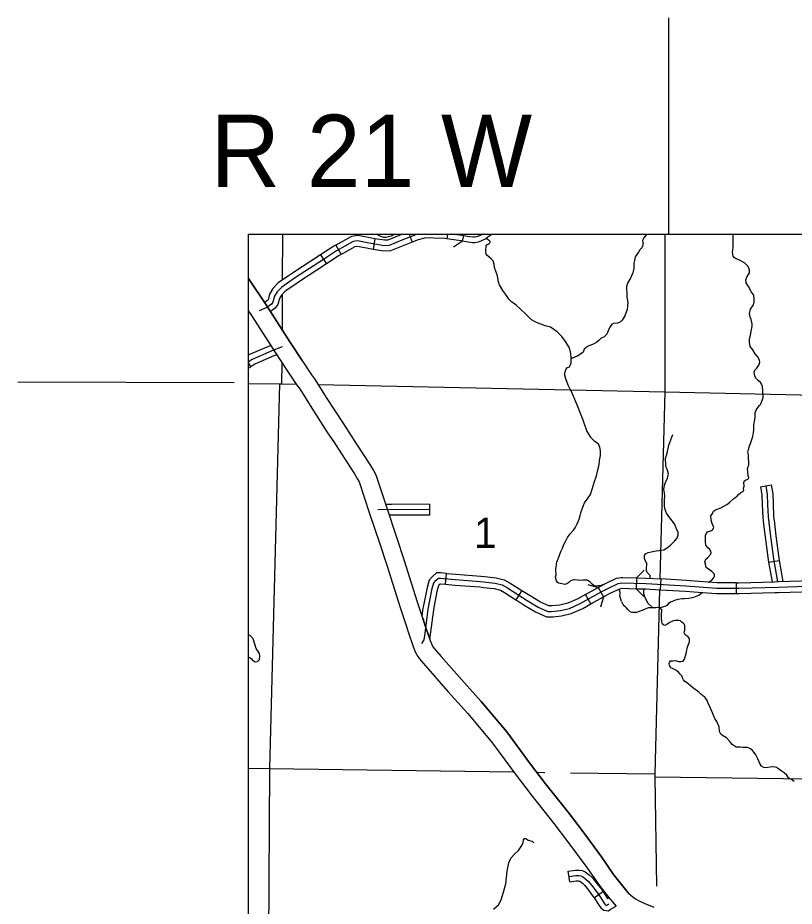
# Model space of a CAD drawing. Extents: x 813775 to 1157140, y 1757555 to 1979907.
# Drawn here: x 906132 to 927663, y 1862069 to 1886709 of the extents above; entities that cross this region are included whole.
import ezdxf

# ---------------------------------------------------------------- set-up
doc = ezdxf.new("R2010")
doc.units = 0
for name, color, linetype in [('Level 10', 7, 'Continuous'), ('Level 31', 7, 'Continuous'), ('Level 32', 7, 'Continuous'), ('Level 35', 7, 'Continuous'), ('Level 38', 7, 'Continuous'), ('Level 4', 7, 'Continuous'), ('Level 45', 7, 'Continuous'), ('Level 5', 7, 'Continuous'), ('R_Dimension', 7, 'Continuous'), ('R_Draft', 7, 'Continuous')]:
    doc.layers.add(name, color=color, linetype=linetype)

msp = doc.modelspace()

# ---------------------------------------------------------------- linework, layer by layer
at = {"layer": 'Level 10'}
for p, q in [((914014, 1877207), (914013, 1877209)), ((916840, 1871686), (916841, 1871683)), ((916840, 1871686), (916841, 1871683)), ((918436, 1868354), (918434, 1868357)), ((923059, 1862439), (923199, 1862322)), ((923199, 1862322), (923190, 1862329))]:
    msp.add_line(p, q, dxfattribs=at)
for points in [[(912532, 1879482), (913034, 1878721), (913678, 1877720), (914014, 1877207)], [(914014, 1877207), (913678, 1877720), (913034, 1878721), (912532, 1879482)], [(912532, 1878574), (912615, 1878448), (913259, 1877447), (913596, 1876933)], [(912532, 1878574), (912615, 1878448), (913259, 1877447), (913596, 1876933)], [(912532, 1878574), (912615, 1878448), (913259, 1877447), (913596, 1876933)], [(914013, 1877209), (914281, 1876809), (914364, 1876696), (914704, 1876152), (915143, 1875474), (915313, 1875217), (915527, 1874885), (915898, 1874321), (915995, 1874153), (916057, 1874032), (916354, 1873144), (916646, 1872279), (916840, 1871686)], [(914013, 1877209), (914281, 1876809), (914364, 1876696), (914704, 1876152), (915143, 1875474), (915313, 1875217), (915527, 1874885), (915898, 1874321), (915995, 1874153), (916057, 1874032), (916354, 1873144), (916646, 1872279), (916840, 1871686)], [(913596, 1876933), (913872, 1876521), (913950, 1876415), (914282, 1875883), (914724, 1875200), (914894, 1874944), (915108, 1874612), (915472, 1874058), (915556, 1873914), (915595, 1873838), (915880, 1872985), (916172, 1872122), (916364, 1871531)], [(913596, 1876933), (913872, 1876521), (913950, 1876415), (914282, 1875883), (914724, 1875200), (914894, 1874944), (915108, 1874612), (915472, 1874058), (915556, 1873914), (915595, 1873838), (915880, 1872985), (916172, 1872122), (916364, 1871531)], [(913596, 1876933), (913872, 1876521), (913950, 1876415), (914282, 1875883), (914724, 1875200), (914894, 1874944), (915108, 1874612), (915472, 1874058), (915556, 1873914), (915595, 1873838), (915880, 1872985), (916172, 1872122), (916364, 1871531)], [(916841, 1871683), (917207, 1870512), (917359, 1870068), (917359, 1870067), (917361, 1870062), (917364, 1870051), (917370, 1870038), (917431, 1869832), (917570, 1869441), (917611, 1869325), (917646, 1869261), (917650, 1869256), (917692, 1869204), (917877, 1868992), (918436, 1868354)], [(916841, 1871683), (917207, 1870512), (917359, 1870068), (917359, 1870067), (917361, 1870062), (917364, 1870051), (917370, 1870038), (917431, 1869832), (917570, 1869441), (917611, 1869325), (917646, 1869261), (917650, 1869256), (917692, 1869204), (917877, 1868992), (918436, 1868354)], [(916364, 1871531), (916732, 1870356), (916894, 1869885), (916956, 1869677), (917099, 1869273), (917154, 1869120), (917221, 1868997), (917250, 1868955), (917309, 1868882), (917501, 1868663), (918060, 1868025)], [(916364, 1871531), (916732, 1870356), (916894, 1869885), (916956, 1869677), (917099, 1869273), (917154, 1869120), (917221, 1868997), (917250, 1868955), (917309, 1868882), (917501, 1868663), (918060, 1868025)], [(916364, 1871531), (916732, 1870356), (916894, 1869885), (916956, 1869677), (917099, 1869273), (917154, 1869120), (917221, 1868997), (917250, 1868955), (917309, 1868882), (917501, 1868663), (918060, 1868025)], [(918434, 1868357), (918986, 1867743), (919693, 1866904), (920352, 1866007), (920764, 1865465), (921391, 1864674), (921780, 1864165), (922317, 1863435), (922652, 1862952), (922801, 1862763), (922945, 1862584), (923061, 1862437)], [(923061, 1862437), (922945, 1862584), (922801, 1862763), (922652, 1862952), (922317, 1863435), (921780, 1864165), (921391, 1864674), (920764, 1865465), (920352, 1866007), (919693, 1866904), (918986, 1867743), (918434, 1868357)], [(918060, 1868025), (918608, 1867414), (919300, 1866594), (919952, 1865708), (920369, 1865158), (920996, 1864367), (921380, 1863865), (921911, 1863144), (922250, 1862655), (922410, 1862452), (922557, 1862269), (922721, 1862069)], [(918060, 1868025), (918608, 1867414), (919300, 1866594), (919952, 1865708), (920369, 1865158), (920996, 1864367), (921380, 1863865), (921911, 1863144), (922250, 1862655), (922410, 1862452), (922557, 1862269), (922706, 1862088)], [(918060, 1868025), (918608, 1867414), (919300, 1866594), (919952, 1865708), (920369, 1865158), (920996, 1864367), (921380, 1863865), (921911, 1863144), (922250, 1862655), (922410, 1862452), (922557, 1862269), (922721, 1862069)], [(923190, 1862329), (923261, 1862276), (923325, 1862235), (923378, 1862207), (923520, 1862147), (923769, 1862044)]]:
    msp.add_lwpolyline(points, dxfattribs=at)
at = {"layer": 'Level 31'}
for p, q in [((914527, 1880134), (914690, 1879883)), ((917992, 1871002), (918021, 1871300))]:
    msp.add_line(p, q, dxfattribs=at)
for points in [[(914527, 1880134), (913749, 1879629), (913640, 1879553)], [(914608, 1880009), (913833, 1879504), (913453, 1879241), (913329, 1879112), (913253, 1878987), (913208, 1878826), (913164, 1878763), (913034, 1878674), (912825, 1878585)], [(914690, 1879883), (913916, 1879380), (913811, 1879307)], [(913640, 1879553), (913356, 1879356), (913209, 1879204), (913114, 1879047), (913071, 1878891), (913057, 1878872), (912973, 1878814)], [(913811, 1879307), (913551, 1879126), (913448, 1879019), (913392, 1878926), (913346, 1878760), (913270, 1878655), (913136, 1878562)], [(913811, 1879307), (913551, 1879126), (913448, 1879019), (913392, 1878926), (913346, 1878760), (913270, 1878655), (913143, 1878567)], [(918021, 1871300), (917866, 1871316), (917745, 1871316), (917628, 1871214), (917536, 1871110), (917481, 1870911), (917384, 1870414)], [(918021, 1871300), (918275, 1871275), (918973, 1871222), (919075, 1871211)], [(919075, 1871211), (919394, 1871176), (919622, 1871120), (919786, 1871033), (920109, 1870822)], [(922227, 1870911), (922257, 1870928), (922444, 1871029), (922736, 1871163), (922868, 1871187), (922902, 1871186)], [(922902, 1871186), (923288, 1871176), (923283, 1870876)], [(923288, 1871176), (923565, 1871169), (923962, 1871146)], [(917678, 1870356), (917773, 1870842), (917807, 1870964), (917840, 1871001), (917856, 1871015), (917992, 1871002)], [(917992, 1871002), (918249, 1870976), (918946, 1870923), (919042, 1870912)], [(919042, 1870912), (919342, 1870880), (919514, 1870838), (919633, 1870774), (919944, 1870571)], [(921877, 1870717), (922227, 1870911)], [(922227, 1870911), (922373, 1870649), (922402, 1870665), (922578, 1870760), (922827, 1870875), (922891, 1870886), (922894, 1870886)], [(926061, 1871040), (926127, 1871040), (927113, 1871068)], [(927113, 1871068), (927222, 1871071), (928168, 1871101)], [(922894, 1870886), (923283, 1870876)], [(923283, 1870876), (923552, 1870869), (923945, 1870847)], [(926061, 1870740), (926132, 1870740), (927121, 1870768)], [(927121, 1870768), (927231, 1870771), (928177, 1870802)], [(917384, 1870414), (917368, 1870336), (917340, 1870123), (917424, 1869857), (917431, 1869832), (917437, 1869816), (917462, 1869747), (917518, 1869588), (917554, 1869486)], [(922023, 1870455), (922373, 1870649)], [(917554, 1869486), (917576, 1869609), (917665, 1870288), (917678, 1870356)]]:
    msp.add_lwpolyline(points, dxfattribs=at)
at = {"layer": 'Level 32'}
for p, q in [((916035, 1880582), (915983, 1880287)), ((916984, 1880709), (917070, 1880490)), ((918046, 1880709), (918028, 1880577)), ((914949, 1880403), (915095, 1880141)), ((912532, 1877117), (912593, 1877028)), ((921444, 1862746), (921397, 1863042)), ((922116, 1862300), (922359, 1862477))]:
    msp.add_line(p, q, dxfattribs=at)
for points in [[(917232, 1880709), (917190, 1880698), (916780, 1880538), (916432, 1880395), (916290, 1880386), (915826, 1880466), (915549, 1880520), (915433, 1880502), (914970, 1880243), (914608, 1880009)], [(916035, 1880582), (915853, 1880614), (915552, 1880672), (915384, 1880646), (914949, 1880403)], [(916807, 1880709), (916724, 1880677), (916398, 1880543), (916298, 1880537), (916035, 1880582)], [(918028, 1880577), (917972, 1880584), (917673, 1880593), (917445, 1880609), (917237, 1880555), (917070, 1880490)], [(918459, 1880515), (918424, 1880522), (918285, 1880541), (918028, 1880577)], [(918450, 1880670), (918305, 1880689), (918164, 1880709)], [(919033, 1880709), (919029, 1880706), (918931, 1880660), (918855, 1880634), (918793, 1880621), (918751, 1880621), (918593, 1880640), (918450, 1880670)], [(918499, 1880709), (918459, 1880515)], [(919162, 1880620), (919108, 1880577), (918987, 1880521), (918896, 1880489), (918809, 1880471), (918741, 1880471), (918569, 1880492), (918459, 1880515)], [(919255, 1880709), (919233, 1880675), (919162, 1880620)], [(914949, 1880403), (914892, 1880372), (914527, 1880135)], [(915983, 1880287), (915799, 1880319), (915546, 1880368), (915483, 1880358), (915095, 1880141)], [(917070, 1880490), (916836, 1880398), (916466, 1880247), (916281, 1880235), (915983, 1880287)], [(915095, 1880141), (915047, 1880115), (914690, 1879883)], [(913146, 1877623), (912557, 1877367), (912532, 1877350)], [(913313, 1877364), (913230, 1877333), (912703, 1877104), (912593, 1877028)], [(912593, 1877028), (912542, 1876992), (912532, 1876981)], [(921397, 1863042), (921595, 1863074), (921703, 1863074), (921783, 1863057), (921865, 1863027), (921980, 1862938), (922072, 1862854), (922194, 1862695), (922314, 1862539), (922359, 1862477)], [(921420, 1862894), (921607, 1862924), (921687, 1862924), (921742, 1862912), (921792, 1862894), (921883, 1862823), (921961, 1862753), (922075, 1862604), (922194, 1862449), (922280, 1862330), (922372, 1862184), (922415, 1862122), (922442, 1862102), (922470, 1862099), (922495, 1862115), (922526, 1862133)], [(921444, 1862746), (921619, 1862774), (921672, 1862774), (921701, 1862768), (921719, 1862761), (921787, 1862709), (921850, 1862651), (921956, 1862513), (922073, 1862359), (922116, 1862300)], [(922116, 1862300), (922156, 1862246), (922247, 1862101), (922306, 1862017), (922387, 1861956), (922508, 1861946), (922571, 1861986), (922721, 1862069)], [(922359, 1862477), (922405, 1862414), (922487, 1862283), (922526, 1862309)]]:
    msp.add_lwpolyline(points, dxfattribs=at)
at = {"layer": 'Level 35'}
for points in [[(916280, 1880618), (916202, 1880640), (916125, 1880684), (916083, 1880709)], [(916589, 1880709), (916568, 1880703), (916487, 1880655), (916371, 1880620), (916336, 1880615), (916280, 1880618)], [(919215, 1880523), (919188, 1880544), (919160, 1880568), (919135, 1880598)], [(919214, 1880462), (919223, 1880474), (919232, 1880485), (919232, 1880494), (919230, 1880503), (919225, 1880513), (919215, 1880523)], [(923571, 1880709), (923570, 1880699), (923530, 1880651), (923488, 1880606), (923459, 1880531), (923469, 1880478), (923470, 1880477)], [(925974, 1880343), (925971, 1880520), (925966, 1880658), (925978, 1880709)], [(919397, 1879655), (919355, 1879781), (919342, 1879866), (919310, 1879967), (919257, 1880023), (919193, 1880076), (919140, 1880121), (919116, 1880153), (919111, 1880214), (919111, 1880286), (919119, 1880358), (919124, 1880387), (919143, 1880408), (919172, 1880427), (919201, 1880446), (919214, 1880462)], [(923470, 1880477), (923456, 1880378), (923435, 1880327), (923384, 1880269), (923342, 1880213), (923296, 1880146), (923254, 1880075), (923230, 1879974), (923211, 1879899), (923219, 1879769)], [(926329, 1879356), (926324, 1879445), (926351, 1879516), (926396, 1879591), (926420, 1879636), (926422, 1879721), (926385, 1879809), (926295, 1879902), (926167, 1879979), (926077, 1880019), (926003, 1880053), (925966, 1880101), (925952, 1880197), (925974, 1880343)], [(923219, 1879769), (923188, 1879634), (923116, 1879470), (923047, 1879369), (923012, 1879257), (923007, 1879193), (923023, 1879058), (923023, 1878957), (923049, 1878813), (923039, 1878707), (923034, 1878614), (922964, 1878444)], [(920902, 1878129), (920757, 1878167), (920516, 1878254), (920380, 1878331), (920213, 1878494), (920075, 1878627), (919955, 1878741), (919878, 1878791), (919830, 1878826), (919785, 1878868), (919753, 1878906), (919700, 1878980), (919586, 1879148), (919488, 1879307), (919461, 1879379), (919448, 1879501), (919427, 1879581), (919397, 1879655)], [(926425, 1878506), (926452, 1878627), (926531, 1878744), (926550, 1878835), (926555, 1878909), (926539, 1879015), (926481, 1879100), (926391, 1879255), (926329, 1879356)], [(922964, 1878444), (922894, 1878320), (922838, 1878264), (922761, 1878238), (922647, 1878227), (922609, 1878209), (922554, 1878124), (922500, 1878025), (922469, 1877932), (922392, 1877860), (922312, 1877823), (922254, 1877765), (922179, 1877706), (922089, 1877653)], [(926704, 1877216), (926643, 1877318), (926582, 1877387), (926513, 1877496), (926438, 1877595), (926420, 1877714), (926420, 1877807), (926446, 1877895), (926465, 1878020), (926497, 1878145), (926497, 1878225), (926473, 1878339), (926444, 1878408), (926425, 1878506)], [(921473, 1877265), (921467, 1877395), (921430, 1877552), (921316, 1877735), (921220, 1877874), (921085, 1877999), (920902, 1878129)], [(922089, 1877653), (921927, 1877592), (921842, 1877517), (921810, 1877435), (921736, 1877382), (921645, 1877321), (921513, 1877270), (921473, 1877265)], [(921472, 1876370), (921398, 1876524), (921326, 1876695), (921297, 1876833), (921318, 1876912), (921329, 1876958), (921377, 1877006), (921430, 1877032), (921448, 1877069), (921475, 1877144), (921473, 1877265)], [(926749, 1876034), (926786, 1876123), (926802, 1876182), (926800, 1876227), (926792, 1876362), (926784, 1876487), (926736, 1876588), (926667, 1876652), (926608, 1876708), (926571, 1876766), (926558, 1876838), (926553, 1876878), (926574, 1876934), (926624, 1876995), (926661, 1877043), (926688, 1877091), (926707, 1877154), (926704, 1877216)], [(921472, 1876370), (921624, 1876002), (921804, 1875555), (921910, 1875234), (922014, 1875082), (922131, 1874957)], [(926539, 1875275), (926545, 1875409), (926561, 1875524), (926584, 1875619), (926582, 1875675), (926584, 1875763), (926603, 1875824), (926638, 1875877), (926701, 1875952), (926736, 1875991), (926749, 1876034)], [(924103, 1874307), (924095, 1874486), (924135, 1874638), (924185, 1874856), (924297, 1875156)], [(926449, 1874898), (926489, 1875015), (926515, 1875097), (926534, 1875211), (926539, 1875275)], [(922261, 1874428), (922295, 1874571), (922292, 1874699), (922276, 1874802), (922234, 1874888), (922131, 1874957)], [(926401, 1874300), (926407, 1874395), (926399, 1874480), (926391, 1874584), (926375, 1874661), (926393, 1874738), (926425, 1874837), (926449, 1874898)], [(922111, 1873825), (922178, 1874004), (922214, 1874170), (922243, 1874272), (922257, 1874335), (922262, 1874391), (922261, 1874428)], [(924065, 1873333), (924074, 1873453), (924063, 1873528), (924044, 1873639), (924063, 1873740), (924103, 1873844), (924151, 1873935), (924158, 1873990), (924172, 1874057), (924161, 1874126), (924135, 1874187), (924108, 1874246), (924103, 1874307)], [(926385, 1874006), (926375, 1874125), (926367, 1874204), (926385, 1874266), (926401, 1874300)], [(925878, 1873276), (925982, 1873365), (926029, 1873402), (926080, 1873440), (926120, 1873485), (926175, 1873530), (926252, 1873581), (926263, 1873618), (926258, 1873666), (926271, 1873716), (926274, 1873756), (926268, 1873793), (926266, 1873825), (926282, 1873868), (926322, 1873892), (926361, 1873902), (926393, 1873923), (926404, 1873961), (926385, 1874006), (926385, 1874027)], [(921748, 1872977), (921780, 1873093), (921817, 1873183), (921846, 1873259), (921945, 1873395), (922012, 1873492), (922063, 1873634), (922111, 1873825)], [(924355, 1872202), (924405, 1872264), (924445, 1872360), (924442, 1872432), (924397, 1872538), (924341, 1872676), (924217, 1872844), (924124, 1872969), (924084, 1873070), (924065, 1873168), (924065, 1873333)], [(925400, 1872507), (925432, 1872569), (925416, 1872622), (925390, 1872688), (925358, 1872773), (925350, 1872893), (925392, 1872962), (925427, 1873026), (925480, 1873063), (925631, 1873121), (925706, 1873161), (925791, 1873212), (925878, 1873276)], [(921374, 1872291), (921440, 1872390), (921541, 1872497), (921584, 1872568), (921644, 1872674), (921703, 1872802), (921730, 1872903), (921748, 1872977)], [(925263, 1871743), (925339, 1871821), (925358, 1871869), (925352, 1871914), (925318, 1871959), (925268, 1872012), (925212, 1872084), (925201, 1872180), (925201, 1872243), (925201, 1872302), (925204, 1872352), (925220, 1872400), (925262, 1872451), (925368, 1872488), (925400, 1872507)], [(921083, 1871607), (921146, 1871779), (921192, 1871908), (921233, 1871998), (921270, 1872101), (921321, 1872183), (921374, 1872291)], [(923548, 1871618), (923511, 1871710), (923511, 1871755), (923513, 1871798), (923543, 1871840), (923617, 1871883), (923744, 1871904), (923835, 1871925), (924047, 1871957), (924143, 1872010), (924236, 1872085), (924355, 1872202)], [(921654, 1871108), (921568, 1871125), (921544, 1871118), (921463, 1871090), (921410, 1871046), (921358, 1871013), (921306, 1870996), (921269, 1870997), (921220, 1871013), (921127, 1871030), (921096, 1871050), (921070, 1871093), (921049, 1871154), (921041, 1871204), (921059, 1871261), (921058, 1871296), (921051, 1871361), (921054, 1871405), (921065, 1871491), (921066, 1871529), (921074, 1871566), (921083, 1871607), (921090, 1871638)], [(925274, 1871059), (925371, 1871104), (925427, 1871165), (925456, 1871223), (925451, 1871282), (925376, 1871351), (925315, 1871396), (925225, 1871468), (925201, 1871555), (925185, 1871617), (925209, 1871694), (925263, 1871743)], [(923667, 1871163), (923665, 1871245), (923630, 1871280), (923588, 1871323), (923567, 1871370), (923567, 1871434), (923580, 1871549), (923575, 1871583), (923548, 1871618)], [(922113, 1870951), (922056, 1870999), (922011, 1871043), (921954, 1871093), (921921, 1871108), (921888, 1871116), (921804, 1871112), (921703, 1871105), (921654, 1871108)], [(922371, 1870989), (922286, 1870953), (922233, 1870952), (922184, 1870949), (922113, 1870951)], [(922875, 1870523), (922850, 1870589), (922829, 1870682), (922837, 1870731), (922838, 1870771), (922804, 1870870)], [(923731, 1870353), (923617, 1870469), (923535, 1870608), (923492, 1870732), (923490, 1870788), (923492, 1870831)], [(923492, 1870831), (923510, 1870871)], [(923928, 1870348), (924074, 1870387), (924153, 1870422), (924193, 1870486), (924233, 1870512), (924300, 1870531), (924350, 1870557), (924440, 1870589), (924544, 1870600), (924621, 1870600), (924738, 1870613), (924879, 1870645), (925017, 1870698), (925113, 1870771)], [(922875, 1870523), (922923, 1870432), (922974, 1870384)], [(923269, 1870217), (923209, 1870218), (923160, 1870219), (923115, 1870233), (923079, 1870271), (923053, 1870296), (923011, 1870348), (922974, 1870384)], [(923269, 1870217), (923474, 1870292), (923620, 1870353), (923731, 1870353), (923829, 1870356), (923893, 1870361), (923928, 1870348), (923981, 1870308), (923986, 1870260), (923976, 1870170), (923970, 1870058), (923981, 1869973), (923994, 1869917), (924045, 1869872), (924087, 1869867), (924146, 1869899), (924182, 1869930)], [(924634, 1869599), (924616, 1869635), (924615, 1869669), (924617, 1869699), (924625, 1869719), (924628, 1869760), (924633, 1869795), (924632, 1869827), (924632, 1869851), (924620, 1869880), (924589, 1869908), (924548, 1869948), (924512, 1869982), (924468, 1869992), (924413, 1869997), (924362, 1869997), (924308, 1869986), (924269, 1869968), (924206, 1869937), (924182, 1869930)], [(912744, 1869217), (912657, 1869489), (912584, 1869567), (912532, 1869595)], [(924381, 1868614), (924283, 1868658), (924243, 1868685), (924203, 1868746), (924198, 1868799), (924201, 1868833), (924230, 1868871), (924299, 1868876), (924365, 1868884), (924453, 1868855), (924517, 1868855), (924581, 1868868), (924620, 1868918), (924650, 1869017), (924671, 1869115), (924692, 1869224), (924719, 1869309), (924761, 1869402), (924761, 1869434), (924761, 1869482), (924719, 1869538), (924634, 1869599)], [(912532, 1868972), (912548, 1868974), (912606, 1868936), (912640, 1868895), (912719, 1868849), (912782, 1868861), (912836, 1868916), (912843, 1869006), (912833, 1869074), (912802, 1869132), (912744, 1869217)], [(925782, 1866737), (925672, 1866802), (925626, 1866844), (925586, 1866918), (925582, 1867044), (925513, 1867188), (925459, 1867274), (925393, 1867437), (925345, 1867564), (925270, 1867724), (925246, 1867771), (925212, 1867830), (925180, 1867867), (925132, 1867907), (925061, 1867960), (925013, 1868005), (924845, 1868133), (924715, 1868250), (924617, 1868314), (924588, 1868346), (924572, 1868388), (924545, 1868455), (924503, 1868508), (924458, 1868558), (924381, 1868614)], [(927663, 1865528), (927584, 1865581), (927507, 1865628), (927456, 1865701), (927379, 1865765), (927296, 1865823), (927222, 1865881), (927169, 1865913), (927094, 1865934), (926999, 1865924), (926879, 1865908), (926821, 1865921), (926754, 1865958), (926707, 1866027), (926683, 1866089), (926651, 1866155), (926600, 1866269), (926553, 1866336), (926505, 1866386), (926454, 1866431), (926364, 1866471), (926239, 1866474), (926173, 1866479), (926056, 1866479), (925942, 1866551), (925883, 1866628), (925782, 1866737)], [(919749, 1863272), (919803, 1863399), (919915, 1863522), (920021, 1863617), (920111, 1863757), (920147, 1863837), (920159, 1863910), (920184, 1863944), (920215, 1863951), (920239, 1863937), (920281, 1863905), (920353, 1863886), (920394, 1863871), (920419, 1863847), (920442, 1863841)], [(919321, 1861985), (919465, 1862111), (919538, 1862249), (919603, 1862455), (919664, 1862695), (919683, 1862869), (919703, 1863046), (919749, 1863272)]]:
    msp.add_lwpolyline(points, dxfattribs=at)
at = {"layer": 'Level 38'}
for points in [[(918460, 1880515), (918210, 1880349)], [(923288, 1871176), (923503, 1871385)], [(921938, 1870996), (922226, 1870913)], [(922371, 1870650), (922287, 1870362)], [(923491, 1870660), (923283, 1870876)]]:
    msp.add_lwpolyline(points, dxfattribs=at)
at = {"layer": 'Level 4'}
for points in [[(924077, 1880709), (924074, 1876331)], [(906132, 1876609), (912132, 1876592)], [(912532, 1876566), (913389, 1876560), (913449, 1876560), (913850, 1876551)], [(914462, 1876538), (924074, 1876331)], [(924074, 1876331), (923939, 1871148)], [(924074, 1876331), (932842, 1876138), (933375, 1876127), (943440, 1876127), (943967, 1876117), (944433, 1876108)], [(923931, 1870847), (923798, 1865737), (923799, 1865658), (923840, 1862624)]]:
    msp.add_lwpolyline(points, dxfattribs=at)
at = {"layer": 'Level 45'}
for p, q in [((926724, 1873703), (927019, 1873758)), ((917548, 1873218), (917548, 1872918)), ((926953, 1871608), (927248, 1871660))]:
    msp.add_line(p, q, dxfattribs=at)
for points in [[(913468, 1877584), (913174, 1877472), (912630, 1877235), (912532, 1877168)], [(926724, 1873703), (926766, 1873475), (926775, 1873209), (926793, 1872852), (926814, 1872664)], [(926871, 1873731), (926916, 1873491), (926925, 1873215), (926942, 1872864), (926996, 1872397), (927089, 1871700), (927200, 1871070)], [(927019, 1873758), (927065, 1873507), (927075, 1873221), (927092, 1872876), (927112, 1872698)], [(916492, 1873215), (916331, 1873215)], [(917548, 1873218), (916492, 1873215)], [(917548, 1873068), (916117, 1873065)], [(916492, 1872915), (916432, 1872915)], [(917548, 1872918), (916492, 1872915)], [(926814, 1872664), (926847, 1872379), (926941, 1871677), (926953, 1871608)], [(927112, 1872698), (927145, 1872416), (927237, 1871723), (927248, 1871660)], [(927248, 1871660), (927351, 1871075)], [(926953, 1871608), (927048, 1871066)], [(917334, 1869357), (917397, 1869459), (917428, 1869632), (917516, 1870312), (917627, 1870877), (917672, 1871037), (917734, 1871108), (917801, 1871166), (917858, 1871166), (918262, 1871126), (918959, 1871072), (919368, 1871028), (919568, 1870979), (919710, 1870903), (920030, 1870694), (920256, 1870548), (920558, 1870366), (920829, 1870246), (920935, 1870246), (921184, 1870272), (921433, 1870330), (921730, 1870463), (922330, 1870797), (922511, 1870894), (922782, 1871019), (922879, 1871037), (923559, 1871019), (924655, 1870957), (925512, 1870890), (926129, 1870890), (927226, 1870921), (928747, 1870970)]]:
    msp.add_lwpolyline(points, dxfattribs=at)
at = {"layer": 'Level 5'}
for p, q in [((923962, 1871146), (923945, 1870847)), ((926061, 1870740), (926061, 1871040)), ((920109, 1870822), (919944, 1870571)), ((922023, 1870455), (921877, 1870717)), ((919944, 1870571), (919944, 1870571))]:
    msp.add_line(p, q, dxfattribs=at)
for points in [[(913476, 1880709), (913467, 1879433)], [(913465, 1879037), (913459, 1878061)], [(913453, 1877140), (913449, 1876560)], [(913389, 1876560), (913113, 1865891)], [(925018, 1871079), (924665, 1871106), (923962, 1871146)], [(926061, 1871040), (925518, 1871040), (925018, 1871079)], [(920946, 1870398), (920927, 1870396), (920861, 1870396), (920627, 1870499), (920336, 1870675), (920111, 1870820), (920109, 1870822)], [(921877, 1870717), (921663, 1870598), (921385, 1870473), (921159, 1870420), (920946, 1870398)], [(923945, 1870847), (924645, 1870807), (924995, 1870780)], [(924995, 1870780), (925506, 1870740), (926061, 1870740)], [(919944, 1870571), (919948, 1870569), (920176, 1870421), (920489, 1870232), (920797, 1870096), (920943, 1870096), (920978, 1870099)], [(920978, 1870099), (921209, 1870124), (921481, 1870187), (921797, 1870329), (922023, 1870455)], [(912532, 1865898), (913113, 1865891)], [(913113, 1865891), (913080, 1861184)], [(913113, 1865891), (919889, 1865793)], [(920522, 1865784), (920746, 1865781)], [(921458, 1865771), (923798, 1865737)], [(923799, 1865658), (933044, 1865537)]]:
    msp.add_lwpolyline(points, dxfattribs=at)
at = {"layer": 'R_Dimension'}
msp.add_line((924173, 1886709), (924173, 1880709), dxfattribs=at)
at = {"layer": 'R_Draft'}
msp.add_lwpolyline([(912532, 1880709), (1062535, 1880709), (1062535, 1798155), (912532, 1798155)], close=True, dxfattribs=at)

# ---------------------------------------------------------------- texts
at = {"layer": 'Level 5'}
msp.add_text('1', height=845, dxfattribs=at).set_placement((918782, 1872002))
at = {"layer": 'R_Draft'}
msp.add_text('R 21 W', height=2000, dxfattribs=at).set_placement((911476, 1882020))

doc.saveas('drawing.dxf')
